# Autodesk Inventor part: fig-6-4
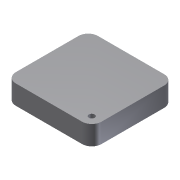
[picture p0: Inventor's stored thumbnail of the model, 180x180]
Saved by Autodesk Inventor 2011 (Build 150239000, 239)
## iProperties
Created: 2004-05
Part Number: fig-6-4
Document SubType Name: Modeling
Designer: CADCIM Technologies
Manufacturer: Standard
Standards Organization: Custom
Density: 1 g/cm^3
Author: CADCIM Technologies
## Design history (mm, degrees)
sketch "Sketch1"
  geometry: L1 (0, 0)-(44.293, 0); L2 (44.293, 0)-(44.293, 42.442); L3 (44.293, 42.442)-(0, 42.442); L4 (0, 42.442)-(0, 0)
  constraints: 8 end point, 2 parallel, 1 horizontal, 1 perpendicular
extrude "Extrusion1" new body sketch "Sketch1" distance "d0" = 10; taper "d1" = 0 deg
fillet "Fillet1" dims "d2" = 5
sketch "Sketch2"
  geometry: 1 further point
sketch "Sketch3"
  geometry: L1 (5, 42.442)-(39.293, 42.442) reference; L2 (0, 5)-(0, 37.442) reference; L3 (39.293, 0)-(5, 0) reference; L4 (44.293, 37.442)-(44.293, 5) reference; A1 r 5 centre (39.293, 37.442) between (44.293, 37.442) and (39.293, 42.442) reference; A2 r 5 centre (5, 37.442) between (5, 42.442) and (0, 37.442) reference; A3 r 5 centre (5, 5) between (0, 5) and (5, 0) reference; A4 r 5 centre (39.293, 5) between (39.293, 0) and (44.293, 5) reference; 1 further point
hole "Hole2" diameter "d15" = 3; stored, may be unused: countersink angle "d19" = 90 deg, drill point angle "d21" = 118 deg; dims "d13" = 10, "d14" = 10, "d16" = 6, "d17" = 4, "d18" = 2, "d20" = 8
body "Solid1"
